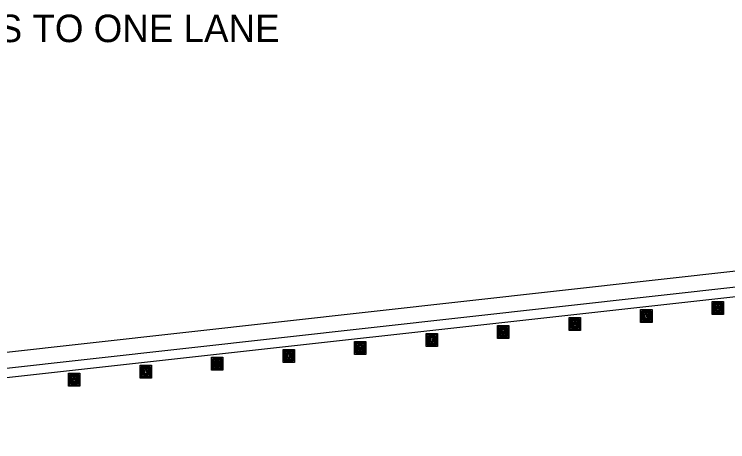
# Model space of a CAD drawing. Extents: x 639362 to 641108, y 298458 to 299646.
# Drawn here: x 639677.2 to 639788.7, y 298620.2 to 298687.1 of the extents above; entities that cross this region are included whole.
import ezdxf

# ---------------------------------------------------------------- set-up
doc = ezdxf.new("R2010")
doc.units = 0
doc.layers.add('2', color=7, linetype='Continuous')

msp = doc.modelspace()

# ---------------------------------------------------------------- linework, layer by layer
at = {"layer": '2'}
for p, q in [((639585.9, 298624.2), (639797.99, 298647.81)), ((639585.9, 298621.7), (639797.99, 298645.31)), ((639585.9, 298620.2), (639797.99, 298643.81)), ((639786.32, 298642.12), (639788.09, 298642.12)), ((639786.32, 298640.08), (639786.32, 298642.12)), ((639788.09, 298642.12), (639788.09, 298640.08)), ((639786.49, 298641.94), (639787.91, 298641.94)), ((639786.49, 298640.26), (639786.49, 298641.94)), ((639786.67, 298641.77), (639787.74, 298641.77)), ((639786.67, 298640.44), (639786.67, 298641.77)), ((639786.85, 298640.62), (639786.85, 298641.59)), ((639786.85, 298641.59), (639787.56, 298641.59)), ((639787.03, 298641.41), (639787.38, 298641.41)), ((639787.03, 298640.79), (639787.03, 298641.41)), ((639787.2, 298641.24), (639787.2, 298640.97)), ((639787.38, 298641.41), (639787.38, 298640.79)), ((639787.56, 298641.59), (639787.56, 298640.62)), ((639787.74, 298641.77), (639787.74, 298640.44)), ((639787.91, 298641.94), (639787.91, 298640.26)), ((639775.13, 298640.88), (639776.91, 298640.88)), ((639775.13, 298638.84), (639775.13, 298640.88)), ((639775.31, 298640.7), (639776.73, 298640.7)), ((639775.31, 298639.01), (639775.31, 298640.7)), ((639775.49, 298640.52), (639776.55, 298640.52)), ((639775.49, 298639.19), (639775.49, 298640.52)), ((639775.67, 298639.37), (639775.67, 298640.34)), ((639775.67, 298640.34), (639776.38, 298640.34)), ((639775.84, 298640.17), (639776.2, 298640.17)), ((639775.84, 298639.55), (639775.84, 298640.17)), ((639776.02, 298639.99), (639776.02, 298639.72)), ((639776.2, 298640.17), (639776.2, 298639.55)), ((639776.38, 298640.34), (639776.38, 298639.37)), ((639776.55, 298640.52), (639776.55, 298639.19)), ((639776.73, 298640.7), (639776.73, 298639.01)), ((639776.91, 298640.88), (639776.91, 298638.84)), ((639788.09, 298640.08), (639786.32, 298640.08)), ((639787.91, 298640.26), (639786.49, 298640.26)), ((639787.74, 298640.44), (639786.67, 298640.44)), ((639787.56, 298640.62), (639786.85, 298640.62)), ((639787.38, 298640.79), (639787.03, 298640.79)), ((639763.95, 298639.63), (639765.73, 298639.63)), ((639763.95, 298637.59), (639763.95, 298639.63)), ((639764.13, 298639.45), (639765.55, 298639.45)), ((639764.13, 298637.77), (639764.13, 298639.45)), ((639764.31, 298639.28), (639765.37, 298639.28)), ((639764.31, 298637.95), (639764.31, 298639.28)), ((639764.48, 298638.12), (639764.48, 298639.1)), ((639764.48, 298639.1), (639765.19, 298639.1)), ((639764.66, 298638.92), (639765.02, 298638.92)), ((639764.66, 298638.3), (639764.66, 298638.92)), ((639764.84, 298638.75), (639764.84, 298638.48)), ((639765.02, 298638.92), (639765.02, 298638.3)), ((639765.19, 298639.1), (639765.19, 298638.12)), ((639765.37, 298639.28), (639765.37, 298637.95)), ((639765.55, 298639.45), (639765.55, 298637.77)), ((639765.73, 298639.63), (639765.73, 298637.59)), ((639776.91, 298638.84), (639775.13, 298638.84)), ((639776.73, 298639.01), (639775.31, 298639.01)), ((639776.55, 298639.19), (639775.49, 298639.19)), ((639776.38, 298639.37), (639775.67, 298639.37)), ((639776.2, 298639.55), (639775.84, 298639.55)), ((639752.77, 298638.39), (639754.54, 298638.39)), ((639752.77, 298636.35), (639752.77, 298638.39)), ((639752.94, 298638.21), (639754.36, 298638.21)), ((639752.94, 298636.52), (639752.94, 298638.21)), ((639753.12, 298638.03), (639754.19, 298638.03)), ((639753.12, 298636.7), (639753.12, 298638.03)), ((639753.3, 298636.88), (639753.3, 298637.85)), ((639753.3, 298637.85), (639754.01, 298637.85)), ((639753.48, 298637.68), (639753.83, 298637.68)), ((639753.48, 298637.06), (639753.48, 298637.68)), ((639753.83, 298637.68), (639753.83, 298637.06)), ((639754.01, 298637.85), (639754.01, 298636.88)), ((639754.19, 298638.03), (639754.19, 298636.7)), ((639754.36, 298638.21), (639754.36, 298636.52)), ((639754.54, 298638.39), (639754.54, 298636.35)), ((639765.73, 298637.59), (639763.95, 298637.59)), ((639765.55, 298637.77), (639764.13, 298637.77)), ((639765.37, 298637.95), (639764.31, 298637.95)), ((639765.19, 298638.12), (639764.48, 298638.12)), ((639765.02, 298638.3), (639764.66, 298638.3)), ((639741.58, 298637.14), (639743.36, 298637.14)), ((639741.58, 298635.1), (639741.58, 298637.14)), ((639741.76, 298636.96), (639743.18, 298636.96)), ((639741.76, 298635.28), (639741.76, 298636.96)), ((639741.94, 298636.79), (639743, 298636.79)), ((639741.94, 298635.46), (639741.94, 298636.79)), ((639742.12, 298635.63), (639742.12, 298636.61)), ((639742.12, 298636.61), (639742.82, 298636.61)), ((639742.29, 298636.43), (639742.65, 298636.43)), ((639742.29, 298635.81), (639742.29, 298636.43)), ((639742.65, 298636.43), (639742.65, 298635.81)), ((639742.82, 298636.61), (639742.82, 298635.63)), ((639743, 298636.79), (639743, 298635.46)), ((639743.18, 298636.96), (639743.18, 298635.28)), ((639743.36, 298637.14), (639743.36, 298635.1)), ((639754.36, 298636.52), (639752.94, 298636.52)), ((639754.19, 298636.7), (639753.12, 298636.7)), ((639754.01, 298636.88), (639753.3, 298636.88)), ((639753.83, 298637.06), (639753.48, 298637.06)), ((639753.65, 298637.5), (639753.65, 298637.23)), ((639730.4, 298635.9), (639732.17, 298635.9)), ((639730.4, 298633.86), (639730.4, 298635.9)), ((639730.58, 298635.72), (639732, 298635.72)), ((639730.58, 298634.03), (639730.58, 298635.72)), ((639730.75, 298635.54), (639731.82, 298635.54)), ((639730.75, 298634.21), (639730.75, 298635.54)), ((639730.93, 298634.39), (639730.93, 298635.36)), ((639730.93, 298635.36), (639731.64, 298635.36)), ((639731.64, 298635.36), (639731.64, 298634.39)), ((639731.82, 298635.54), (639731.82, 298634.21)), ((639732, 298635.72), (639732, 298634.03)), ((639732.17, 298635.9), (639732.17, 298633.86)), ((639743, 298635.46), (639741.94, 298635.46)), ((639742.82, 298635.63), (639742.12, 298635.63)), ((639742.65, 298635.81), (639742.29, 298635.81)), ((639742.47, 298636.26), (639742.47, 298635.99)), ((639754.54, 298636.35), (639752.77, 298636.35)), ((639719.22, 298634.65), (639720.99, 298634.65)), ((639719.22, 298632.61), (639719.22, 298634.65)), ((639719.39, 298634.47), (639720.81, 298634.47)), ((639719.39, 298632.79), (639719.39, 298634.47)), ((639719.57, 298634.3), (639720.64, 298634.3)), ((639719.57, 298632.97), (639719.57, 298634.3)), ((639720.64, 298634.3), (639720.64, 298632.97)), ((639720.81, 298634.47), (639720.81, 298632.79)), ((639720.99, 298634.65), (639720.99, 298632.61)), ((639731.82, 298634.21), (639730.75, 298634.21)), ((639731.64, 298634.39), (639730.93, 298634.39)), ((639731.11, 298635.19), (639731.46, 298635.19)), ((639731.11, 298634.57), (639731.11, 298635.19)), ((639731.46, 298634.57), (639731.11, 298634.57)), ((639731.28, 298635.01), (639731.28, 298634.74)), ((639731.46, 298635.19), (639731.46, 298634.57)), ((639743.36, 298635.1), (639741.58, 298635.1)), ((639743.18, 298635.28), (639741.76, 298635.28)), ((639708.03, 298633.41), (639709.81, 298633.41)), ((639708.03, 298631.37), (639708.03, 298633.41)), ((639708.21, 298633.23), (639709.63, 298633.23)), ((639708.21, 298631.54), (639708.21, 298633.23)), ((639709.63, 298633.23), (639709.63, 298631.54)), ((639709.81, 298633.41), (639709.81, 298631.37)), ((639719.75, 298633.14), (639719.75, 298634.12)), ((639719.75, 298634.12), (639720.46, 298634.12)), ((639720.46, 298633.14), (639719.75, 298633.14)), ((639719.93, 298633.94), (639720.28, 298633.94)), ((639719.93, 298633.32), (639719.93, 298633.94)), ((639720.28, 298633.32), (639719.93, 298633.32)), ((639720.1, 298633.77), (639720.1, 298633.5)), ((639720.28, 298633.94), (639720.28, 298633.32)), ((639720.46, 298634.12), (639720.46, 298633.14)), ((639732.17, 298633.86), (639730.4, 298633.86)), ((639732, 298634.03), (639730.58, 298634.03)), ((639696.85, 298632.16), (639698.62, 298632.16)), ((639696.85, 298630.12), (639696.85, 298632.16)), ((639697.03, 298631.98), (639698.45, 298631.98)), ((639697.03, 298630.3), (639697.03, 298631.98)), ((639698.45, 298631.98), (639698.45, 298630.3)), ((639698.62, 298632.16), (639698.62, 298630.12)), ((639708.39, 298633.05), (639709.45, 298633.05)), ((639708.39, 298631.72), (639708.39, 298633.05)), ((639708.56, 298631.9), (639708.56, 298632.87)), ((639708.56, 298632.87), (639709.27, 298632.87)), ((639708.74, 298632.7), (639709.1, 298632.7)), ((639708.74, 298632.08), (639708.74, 298632.7)), ((639709.1, 298632.08), (639708.74, 298632.08)), ((639708.92, 298632.52), (639708.92, 298632.25)), ((639709.1, 298632.7), (639709.1, 298632.08)), ((639709.27, 298632.87), (639709.27, 298631.9)), ((639709.45, 298633.05), (639709.45, 298631.72)), ((639720.99, 298632.61), (639719.22, 298632.61)), ((639720.81, 298632.79), (639719.39, 298632.79)), ((639720.64, 298632.97), (639719.57, 298632.97)), ((639685.66, 298630.91), (639687.44, 298630.91)), ((639685.66, 298628.88), (639685.66, 298630.91)), ((639687.44, 298630.91), (639687.44, 298628.88)), ((639697.2, 298631.8), (639698.27, 298631.8)), ((639697.2, 298630.48), (639697.2, 298631.8)), ((639697.38, 298630.65), (639697.38, 298631.63)), ((639697.38, 298631.63), (639698.09, 298631.63)), ((639697.56, 298631.45), (639697.91, 298631.45)), ((639697.56, 298630.83), (639697.56, 298631.45)), ((639697.73, 298631.28), (639697.73, 298631.01)), ((639697.91, 298631.45), (639697.91, 298630.83)), ((639698.09, 298631.63), (639698.09, 298630.65)), ((639698.27, 298631.8), (639698.27, 298630.48)), ((639709.81, 298631.37), (639708.03, 298631.37)), ((639709.63, 298631.54), (639708.21, 298631.54)), ((639709.45, 298631.72), (639708.39, 298631.72)), ((639709.27, 298631.9), (639708.56, 298631.9)), ((639685.84, 298630.74), (639687.26, 298630.74)), ((639685.84, 298629.05), (639685.84, 298630.74)), ((639686.02, 298630.56), (639687.08, 298630.56)), ((639686.02, 298629.23), (639686.02, 298630.56)), ((639686.2, 298629.41), (639686.2, 298630.38)), ((639686.2, 298630.38), (639686.91, 298630.38)), ((639686.38, 298630.21), (639686.73, 298630.21)), ((639686.38, 298629.59), (639686.38, 298630.21)), ((639686.55, 298630.03), (639686.55, 298629.76)), ((639686.73, 298630.21), (639686.73, 298629.59)), ((639686.91, 298630.38), (639686.91, 298629.41)), ((639687.08, 298630.56), (639687.08, 298629.23)), ((639687.26, 298630.74), (639687.26, 298629.05)), ((639698.62, 298630.12), (639696.85, 298630.12)), ((639698.45, 298630.3), (639697.03, 298630.3)), ((639698.27, 298630.48), (639697.2, 298630.48)), ((639698.09, 298630.65), (639697.38, 298630.65)), ((639697.91, 298630.83), (639697.56, 298630.83)), ((639687.44, 298628.88), (639685.66, 298628.88)), ((639687.26, 298629.05), (639685.84, 298629.05)), ((639687.08, 298629.23), (639686.02, 298629.23)), ((639686.91, 298629.41), (639686.2, 298629.41)), ((639686.73, 298629.59), (639686.38, 298629.59))]:
    msp.add_line(p, q, dxfattribs=at)

# ---------------------------------------------------------------- texts
msp.add_text('TWO LANES TO ONE LANE', height=4.3, dxfattribs=at).set_placement((639644.55, 298682.71))

doc.saveas('drawing.dxf')
